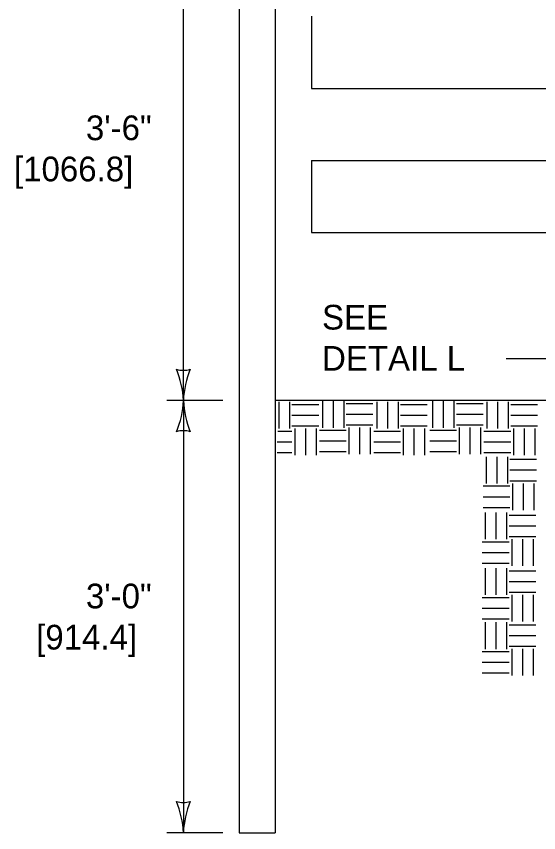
# Model space of a CAD drawing. Extents: x 49991.4 to 50021, y 49987.6 to 50011.4.
# Drawn here: x 50008.465 to 50009.735, y 49995.542 to 49997.525 of the extents above; entities that cross this region are included whole.
import ezdxf

# ---------------------------------------------------------------- set-up
doc = ezdxf.new("R2010")
doc.units = 0
for name, color, linetype in [('Level 1', 7, 'Continuous'), ('Level 2', 7, 'Continuous'), ('Level 3', 7, 'Continuous')]:
    doc.layers.add(name, color=color, linetype=linetype)

msp = doc.modelspace()

# ---------------------------------------------------------------- linework, layer by layer
at = {"layer": 'Level 1'}
for p, q in [((50009.0073, 49997.8169), (50009.0073, 49995.5419)), ((50009.0948, 49997.8169), (50009.0948, 49995.5419)), ((50009.1825, 49997.5253), (50009.1825, 49997.3503)), ((50009.1825, 49997.3503), (50013.9411, 49997.3503)), ((50009.1825, 49997.1753), (50009.1825, 49997.0003)), ((50009.1825, 49997.1753), (50014.1911, 49997.1753)), ((50009.1825, 49997.0003), (50014.7825, 49997.0003)), ((50009.8451, 49996.5919), (50009.0948, 49996.5919)), ((50009.1034, 49996.5884), (50009.1034, 49996.5235)), ((50009.1294, 49996.5884), (50009.1294, 49996.5235)), ((50009.1353, 49996.5824), (50009.2002, 49996.5824)), ((50009.2093, 49996.5904), (50009.2093, 49996.5256)), ((50009.2352, 49996.5904), (50009.2352, 49996.5256)), ((50009.2612, 49996.5904), (50009.2612, 49996.5256)), ((50009.2672, 49996.5844), (50009.332, 49996.5844)), ((50009.3411, 49996.5884), (50009.3411, 49996.5235)), ((50009.3671, 49996.5884), (50009.3671, 49996.5235)), ((50009.393, 49996.5884), (50009.393, 49996.5235)), ((50009.3991, 49996.5824), (50009.4639, 49996.5824)), ((50009.477, 49996.5904), (50009.477, 49996.5256)), ((50009.5029, 49996.5904), (50009.5029, 49996.5256)), ((50009.5289, 49996.5904), (50009.5289, 49996.5256)), ((50009.5349, 49996.5844), (50009.5998, 49996.5844)), ((50009.6089, 49996.5884), (50009.6089, 49996.5235)), ((50009.6348, 49996.5884), (50009.6348, 49996.5235)), ((50009.6608, 49996.5884), (50009.6608, 49996.5235)), ((50009.6668, 49996.5824), (50009.7316, 49996.5824)), ((50009.1353, 49996.5564), (50009.2002, 49996.5564)), ((50009.2672, 49996.5585), (50009.332, 49996.5585)), ((50009.3991, 49996.5564), (50009.4639, 49996.5564)), ((50009.5349, 49996.5585), (50009.5998, 49996.5585)), ((50009.6668, 49996.5564), (50009.7316, 49996.5564)), ((50009.1012, 49996.5175), (50009.1353, 49996.5175)), ((50009.1353, 49996.5305), (50009.2002, 49996.5305)), ((50009.1418, 49996.524), (50009.1418, 49996.4591)), ((50009.1678, 49996.524), (50009.1678, 49996.4591)), ((50009.1937, 49996.524), (50009.1937, 49996.4591)), ((50009.2023, 49996.5195), (50009.2672, 49996.5195)), ((50009.2672, 49996.5325), (50009.332, 49996.5325)), ((50009.2737, 49996.526), (50009.2737, 49996.4612)), ((50009.2996, 49996.526), (50009.2996, 49996.4612)), ((50009.3256, 49996.526), (50009.3256, 49996.4612)), ((50009.3342, 49996.5175), (50009.3991, 49996.5175)), ((50009.3991, 49996.5305), (50009.4639, 49996.5305)), ((50009.4055, 49996.524), (50009.4055, 49996.4591)), ((50009.4315, 49996.524), (50009.4315, 49996.4591)), ((50009.4574, 49996.524), (50009.4574, 49996.4591)), ((50009.47, 49996.5195), (50009.5349, 49996.5195)), ((50009.5349, 49996.5325), (50009.5998, 49996.5325)), ((50009.5414, 49996.526), (50009.5414, 49996.4612)), ((50009.5673, 49996.526), (50009.5673, 49996.4612)), ((50009.5933, 49996.526), (50009.5933, 49996.4612)), ((50009.6019, 49996.5175), (50009.6668, 49996.5175)), ((50009.6668, 49996.5305), (50009.7316, 49996.5305)), ((50009.6733, 49996.524), (50009.6733, 49996.4591)), ((50009.6992, 49996.524), (50009.6992, 49996.4591)), ((50009.7251, 49996.524), (50009.7251, 49996.4591)), ((50009.0992, 49996.4916), (50009.1353, 49996.4916)), ((50009.2023, 49996.4936), (50009.2672, 49996.4936)), ((50009.3342, 49996.4916), (50009.3991, 49996.4916)), ((50009.47, 49996.4936), (50009.5349, 49996.4936)), ((50009.6019, 49996.4916), (50009.6668, 49996.4916)), ((50009.0992, 49996.4656), (50009.1353, 49996.4656)), ((50009.2023, 49996.4676), (50009.2672, 49996.4676)), ((50009.3342, 49996.4656), (50009.3991, 49996.4656)), ((50009.47, 49996.4676), (50009.5349, 49996.4676)), ((50009.6019, 49996.4656), (50009.6668, 49996.4656)), ((50009.6069, 49996.455), (50009.6069, 49996.3902)), ((50009.6328, 49996.455), (50009.6328, 49996.3902)), ((50009.6588, 49996.455), (50009.6588, 49996.3902)), ((50009.6648, 49996.449), (50009.7296, 49996.449)), ((50009.6648, 49996.4231), (50009.7296, 49996.4231)), ((50009.6648, 49996.3971), (50009.7296, 49996.3971)), ((50009.5999, 49996.3842), (50009.6648, 49996.3842)), ((50009.6713, 49996.3906), (50009.6713, 49996.3258)), ((50009.6972, 49996.3906), (50009.6972, 49996.3258)), ((50009.7232, 49996.3906), (50009.7232, 49996.3258)), ((50009.5999, 49996.3582), (50009.6648, 49996.3582)), ((50009.5999, 49996.3323), (50009.6648, 49996.3323)), ((50009.6049, 49996.3197), (50009.6049, 49996.2548)), ((50009.6308, 49996.3197), (50009.6308, 49996.2548)), ((50009.6568, 49996.3197), (50009.6568, 49996.2548)), ((50009.6628, 49996.3137), (50009.7276, 49996.3137)), ((50009.6628, 49996.2877), (50009.7276, 49996.2877)), ((50009.6628, 49996.2618), (50009.7276, 49996.2618)), ((50009.5979, 49996.2488), (50009.6628, 49996.2488)), ((50009.6693, 49996.2553), (50009.6693, 49996.1904)), ((50009.6952, 49996.2553), (50009.6952, 49996.1904)), ((50009.7211, 49996.2553), (50009.7211, 49996.1904)), ((50009.5979, 49996.2229), (50009.6628, 49996.2229)), ((50009.5979, 49996.1969), (50009.6628, 49996.1969)), ((50009.6049, 49996.1844), (50009.6049, 49996.1195)), ((50009.6308, 49996.1844), (50009.6308, 49996.1195)), ((50009.6568, 49996.1844), (50009.6568, 49996.1195)), ((50009.6628, 49996.1784), (50009.7276, 49996.1784)), ((50009.6628, 49996.1524), (50009.7276, 49996.1524)), ((50009.6628, 49996.1265), (50009.7276, 49996.1265)), ((50009.6693, 49996.12), (50009.6693, 49996.0551)), ((50009.6952, 49996.12), (50009.6952, 49996.0551)), ((50009.7211, 49996.12), (50009.7211, 49996.0551)), ((50009.5979, 49996.1135), (50009.6628, 49996.1135)), ((50009.5979, 49996.0875), (50009.6628, 49996.0875)), ((50009.5979, 49996.0616), (50009.6628, 49996.0616)), ((50009.6049, 49996.053), (50009.6049, 49995.9881)), ((50009.6308, 49996.053), (50009.6308, 49995.9881)), ((50009.6568, 49996.053), (50009.6568, 49995.9881)), ((50009.6628, 49996.047), (50009.7276, 49996.047)), ((50009.6628, 49996.021), (50009.7276, 49996.021)), ((50009.5979, 49995.9821), (50009.6628, 49995.9821)), ((50009.6628, 49995.9951), (50009.7276, 49995.9951)), ((50009.6693, 49995.9886), (50009.6693, 49995.9237)), ((50009.6952, 49995.9886), (50009.6952, 49995.9237)), ((50009.7211, 49995.9886), (50009.7211, 49995.9237)), ((50009.5979, 49995.9562), (50009.6628, 49995.9562)), ((50009.5979, 49995.9302), (50009.6628, 49995.9302)), ((50009.0073, 49995.5419), (50009.0948, 49995.5419))]:
    msp.add_line(p, q, dxfattribs=at)
at = {"layer": 'Level 3'}
for p, q in [((50008.8714, 49996.5919), (50008.8714, 49997.8169)), ((50009.6558, 49996.6943), (50009.8807, 49996.6943)), ((50008.9673, 49996.5919), (50008.8314, 49996.5919)), ((50008.8714, 49996.5919), (50008.8714, 49995.5419)), ((50008.9673, 49995.5419), (50008.8314, 49995.5419))]:
    msp.add_line(p, q, dxfattribs=at)
for centre, radius, start, end in [((50008.8714, 49996.7201), 0.0548, 252.1388, 287.8612), ((50008.6387, 49996.5804), 0.233, 2.8273, 22.0772), ((50009.0935, 49996.5827), 0.2223, 157.456, 177.6395), ((50008.6493, 49996.6011), 0.2223, 337.456, 357.6395), ((50009.1041, 49996.6034), 0.233, 182.8273, 202.0772), ((50008.8714, 49996.4637), 0.0548, 72.1388, 107.8612), ((50008.8714, 49995.6701), 0.0548, 252.1388, 287.8612), ((50008.6387, 49995.5304), 0.233, 2.8273, 22.0772), ((50009.0935, 49995.5327), 0.2223, 157.456, 177.6395)]:
    msp.add_arc(centre, radius, start, end, dxfattribs=at)

# ---------------------------------------------------------------- texts
at = {"layer": 'Level 2'}
for s, p in [('3\'-6"', (50008.6345, 49997.2244)), ('[1066.8]', (50008.4596, 49997.1244)), ('SEE', (50009.2083, 49996.7643)), ('DETAIL L', (50009.2083, 49996.6643)), ('3\'-0"', (50008.6345, 49996.0869)), ('[914.4]', (50008.5135, 49995.9869))]:
    msp.add_text(s, height=0.06, dxfattribs=at).set_placement(p)

doc.saveas('drawing.dxf')
